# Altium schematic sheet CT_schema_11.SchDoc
size 382 x 278 mm
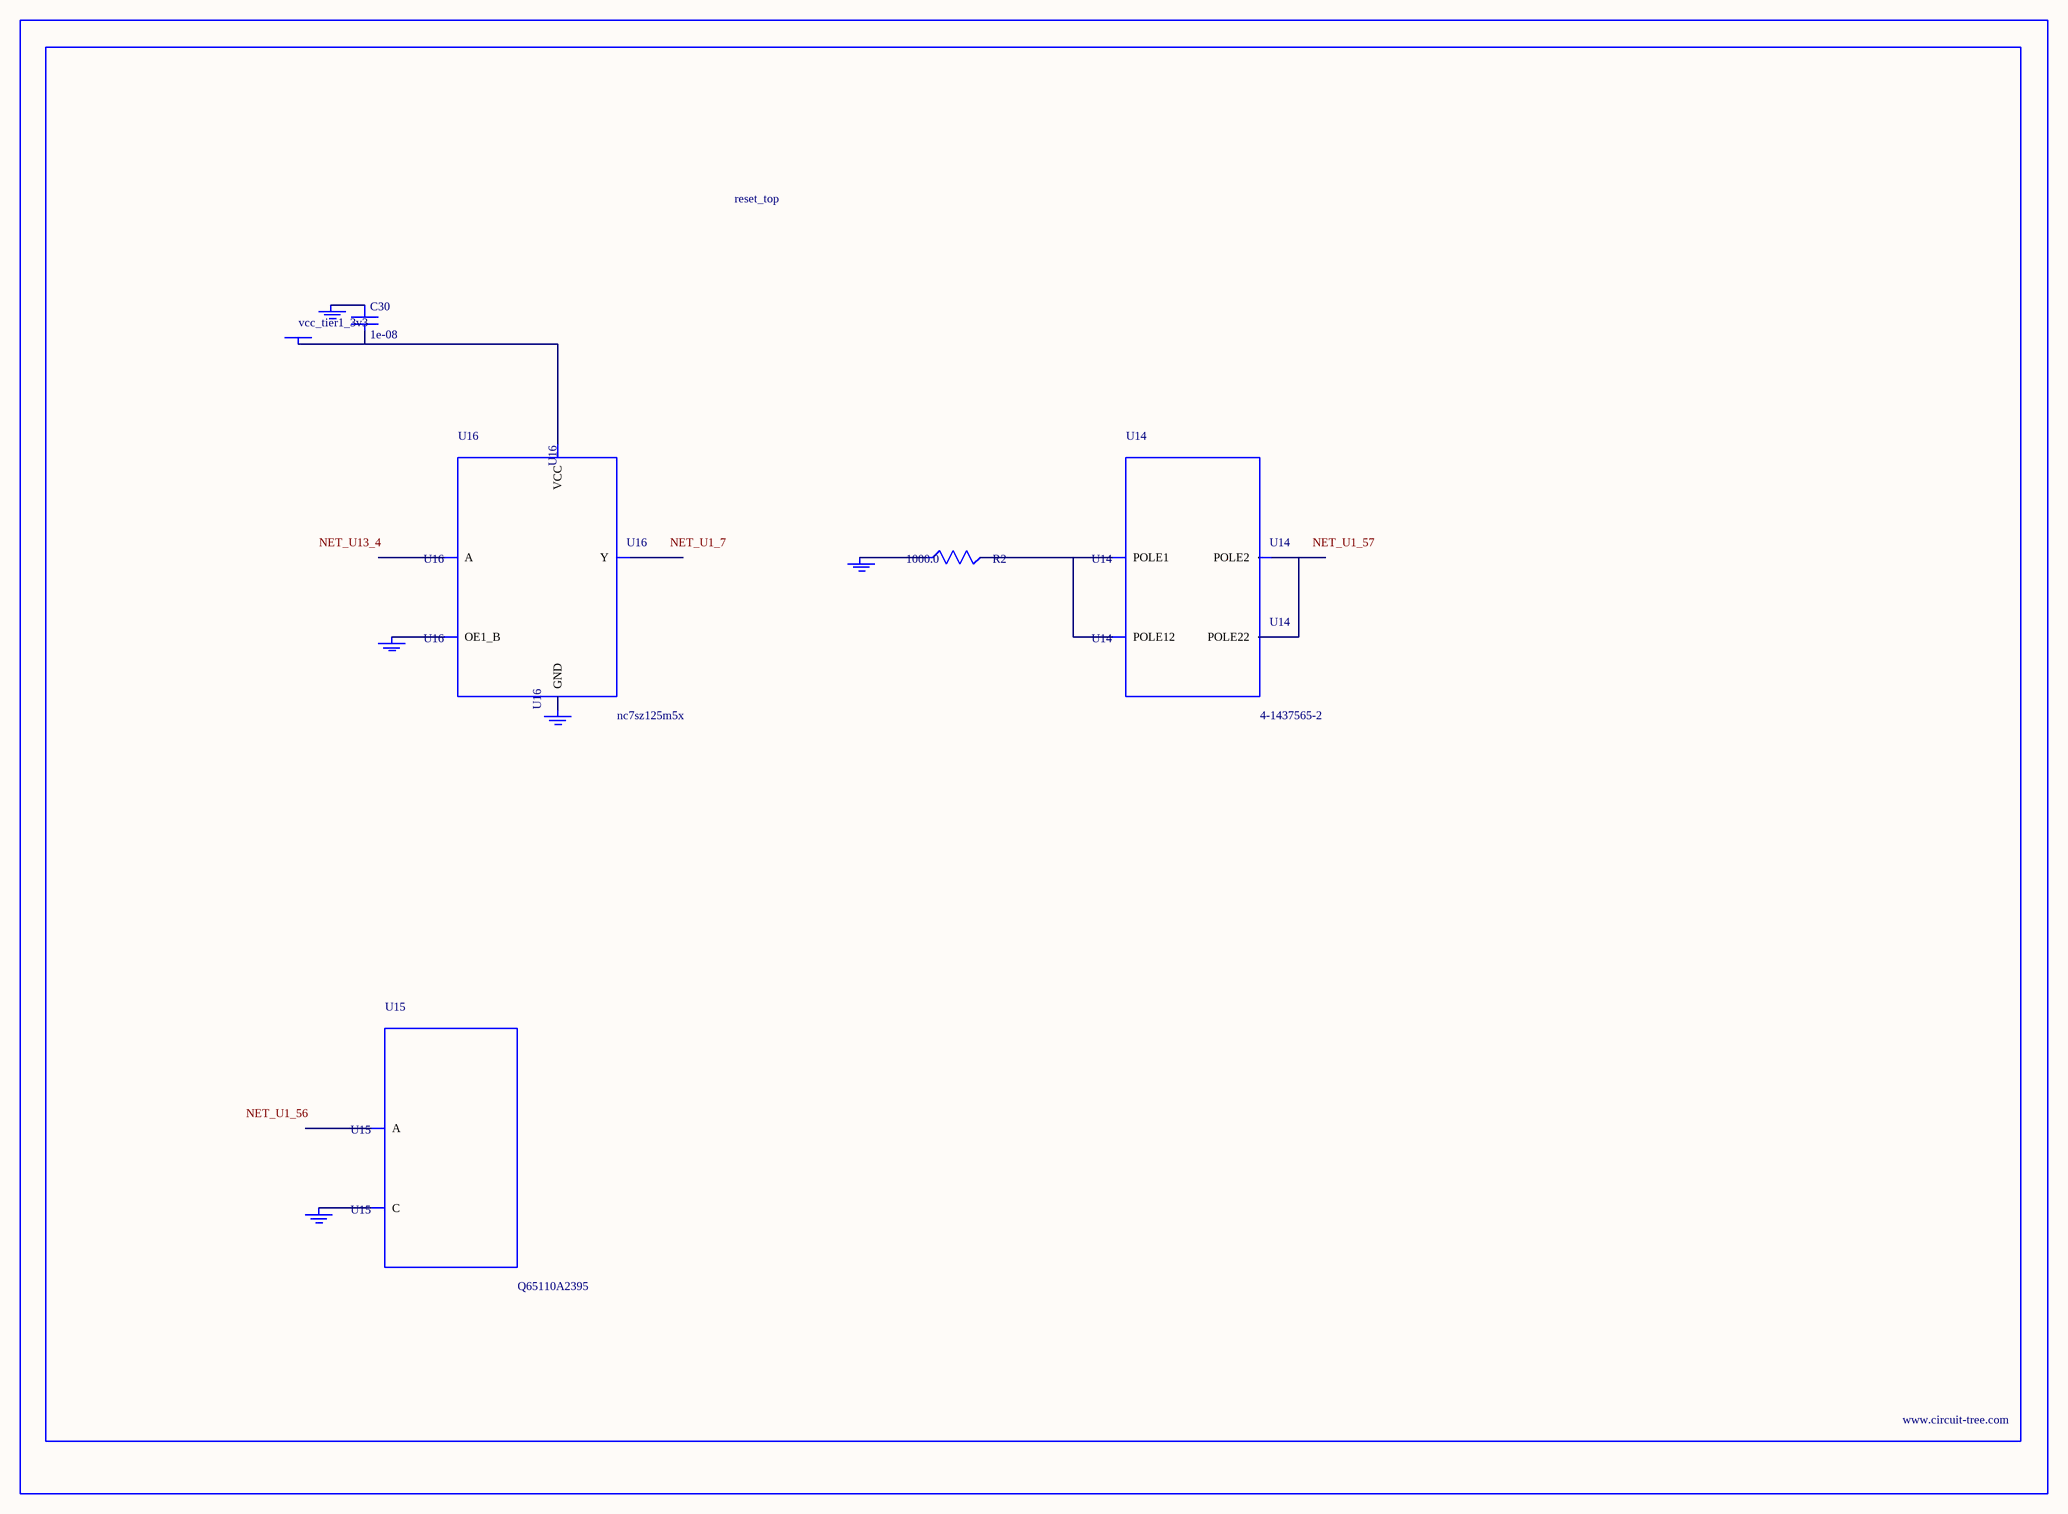
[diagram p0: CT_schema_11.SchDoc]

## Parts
BORDER10  (no value)
C30  1e-08  [C0402]
GND_INSTANCE_10_0  (no value)
GND_INSTANCE_10_1  (no value)
GND_INSTANCE_10_2  (no value)
GND_INSTANCE_10_3  (no value)
GND_INSTANCE_10_4  (no value)
POWER_INSTANCE_10_0  vcc_tier1_3v3
R2  1000.0  [R0603]
U14  4-1437565-2  [SW_4-1437565-2]
U15  Q65110A2395  [LGM67K-G1J2-24-Z]
U16  nc7sz125m5x  [NC7SZ125M5X]

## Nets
NetC30_1: C30.1 GND_INSTANCE_10_2.0(GND)
NetC30_2: C30.2 POWER_INSTANCE_10_0.0(PWR) U16.5(VCC)
NetGND_INSTANCE_10_0_0: GND_INSTANCE_10_0.0(GND) R2.1
NetGND_INSTANCE_10_1_0: GND_INSTANCE_10_1.0(GND) U15.C
NetGND_INSTANCE_10_3_0: GND_INSTANCE_10_3.0(GND) U16.1(OE1_B)
NetGND_INSTANCE_10_4_0: GND_INSTANCE_10_4.0(GND) U16.3(GND)
NetR2_2: R2.2 U14.1(POLE1) U14.2(POLE12)
NetU14_3: U14.3(POLE2) U14.4(POLE22)

Not connected (* = marked no-connect by the designer): U15 A; U16 2(A) 4(Y)

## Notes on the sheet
- Labels drawn without touching a wire or pin: NET_U1_7, NET_U1_56, NET_U1_57, NET_U13_4

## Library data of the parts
BORDER10 = BORDER_PAGE10
C30 = C0402C103K3RAC
GND_INSTANCE_10_0-GND_INSTANCE_10_4 = GND
POWER_INSTANCE_10_0 = PWR
R2 = RC0603JR-071KL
